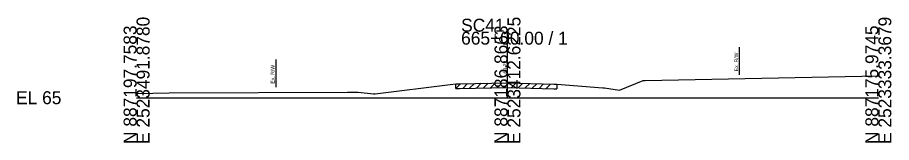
# Model space of a CAD drawing. Extents: x -26 to 183, y -10 to 24021.
# Drawn here: x -25.7 to 162.8, y -9.7 to 17.3 of the extents above; entities that cross this region are included whole.
import ezdxf

# ---------------------------------------------------------------- set-up
doc = ezdxf.new("R2010")
doc.units = 0
for name, color, linetype in [('RD_GPK_XS_Cell', 7, 'Continuous'), ('RD_XS_ExGround', 7, 'Continuous'), ('RD_XS_ExPaveRet', 7, 'Continuous'), ('RD_XS_ExRW', 7, 'Continuous'), ('RD_XS_TX_Elev_EX', 7, 'Continuous')]:
    doc.layers.add(name, color=color, linetype=linetype)

msp = doc.modelspace()

# ---------------------------------------------------------------- linework, layer by layer
at = {"layer": 'RD_GPK_XS_Cell'}
for p, q in [((80, 0), (80, 14.26)), ((0, 0), (80, 0)), ((80, 0), (160, 0))]:
    msp.add_line(p, q, dxfattribs=at)
at = {"layer": 'RD_XS_ExGround'}
for p, q in [((109.69, 3.72), (160, 4.75)), ((51.47, 0.81), (67.61, 2.84)), ((67.61, 2.84), (68.84, 3)), ((68.84, 3), (69.62, 3.01)), ((69.62, 3.01), (80, 3.22)), ((80, 3.22), (89.98, 2.91)), ((89.98, 2.91), (90.67, 2.89)), ((90.67, 2.89), (100.57, 2.16)), ((100.57, 2.16), (100.96, 2.14)), ((100.96, 2.14), (104.2, 1.65)), ((104.2, 1.65), (109.29, 3.71)), ((109.29, 3.71), (109.69, 3.72)), ((0, 0.89), (7, 1.08)), ((7, 1.08), (45.46, 1.16)), ((45.46, 1.16), (47.8, 1.19)), ((47.8, 1.19), (51.11, 0.85)), ((51.11, 0.85), (51.47, 0.81))]:
    msp.add_line(p, q, dxfattribs=at)
at = {"layer": 'RD_XS_ExPaveRet'}
for p, q in [((68.84, 2), (69.85, 3.01)), ((68.84, 2), (68.84, 3)), ((68.84, 2), (69.62, 2.01)), ((69.62, 2.01), (80, 2.22)), ((70.34, 2.02), (71.36, 3.05)), ((71.84, 2.06), (72.86, 3.08)), ((73.34, 2.09), (74.36, 3.11)), ((74.84, 2.12), (75.86, 3.14)), ((76.34, 2.15), (77.36, 3.17)), ((77.84, 2.18), (78.86, 3.2)), ((79.34, 2.21), (80.34, 3.21)), ((80, 2.22), (89.98, 1.91)), ((80.84, 2.2), (81.8, 3.17)), ((82.34, 2.15), (83.3, 3.12)), ((83.84, 2.1), (84.8, 3.07)), ((85.34, 2.06), (86.3, 3.02)), ((86.84, 2.01), (87.8, 2.98)), ((88.34, 1.96), (89.3, 2.93)), ((89.98, 1.91), (90.67, 1.89)), ((90.67, 2.89), (90.67, 1.89))]:
    msp.add_line(p, q, dxfattribs=at)
at = {"layer": 'RD_XS_ExRW'}
for p, q in [((130, 10.92), (130, 4.92)), ((30, 8.26), (30, 2.26))]:
    msp.add_line(p, q, dxfattribs=at)

# ---------------------------------------------------------------- texts
at = {"layer": 'RD_GPK_XS_Cell'}
for s, p in [('E 2523491.8780', (2.8, -10)), ('E 2523412.6225', (82.8, -10)), ('E 2523333.3679', (162.8, -10)), ('N 887197.7583', (0, -10)), ('N 887186.8663', (80, -10)), ('N 887175.9745', (160, -10))]:
    msp.add_text(s, height=2.8, rotation=90, dxfattribs=at).set_placement(p)
for s, p in [('SC41', (70, 14.26)), ('665+00.00 / 1', (70, 11.46)), ('EL 65', (-26, -1.4))]:
    msp.add_text(s, height=2.8, dxfattribs=at).set_placement(p)
at = {"layer": 'RD_XS_ExRW'}
for p in [(129.75, 5.71), (29.75, 3.04)]:
    msp.add_text('Ex. R/W ', height=0.8, rotation=90, dxfattribs=at).set_placement(p)
at = {"layer": 'RD_XS_TX_Elev_EX'}
msp.add_text('68.22', height=0.8, rotation=90, dxfattribs=at).set_placement((79.9, 5.22))

doc.saveas('drawing.dxf')
